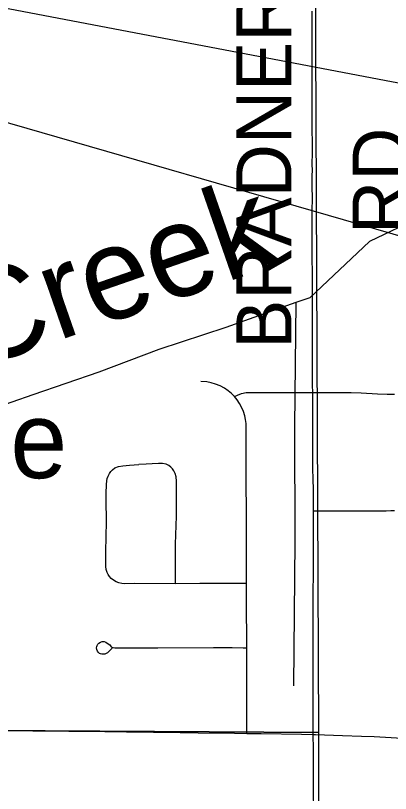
# Model space of a CAD drawing. Extents: x 0 to 34, y 0 to 22.
# Drawn here: x 3.392 to 3.778, y 19.337 to 20.14 of the extents above; entities that cross this region are included whole.
import ezdxf

# ---------------------------------------------------------------- set-up
doc = ezdxf.new("R2010")
doc.units = 0
for name, color, linetype in [('GM_X_Minor_River', 7, 'Continuous'), ('GM_X_Minor_River_Text', 7, 'Continuous'), ('GM_X_Section', 7, 'Continuous'), ('GM_X_Township_Road', 7, 'Continuous'), ('GM_X_Township_Road_Text', 7, 'Continuous'), ('GM_X_Unincorporated_Text', 7, 'Continuous'), ('SH_Text', 7, 'Continuous')]:
    doc.layers.add(name, color=color, linetype=linetype)

msp = doc.modelspace()

# ---------------------------------------------------------------- linework, layer by layer
at = {"layer": 'GM_X_Minor_River'}
for points in [[(3.80864, 19.93128), (3.7568, 19.9067), (3.69535, 19.8485), (3.6809, 19.8438), (3.609, 19.81802), (3.53978, 19.79523), (3.47813, 19.77194), (3.41004, 19.74837), (3.34499, 19.7259)], [(3.6809, 19.8438), (3.67964, 19.71596), (3.68002, 19.59719), (3.67843, 19.44848)]]:
    msp.add_lwpolyline(points, dxfattribs=at)
at = {"layer": 'GM_X_Section'}
for points in [[(3.7003, 20.3485), (3.70416, 19.40015), (2.69072, 19.40645), (2.6925, 20.35134)], [(2.69072, 19.40645), (3.70416, 19.40015), (3.70319, 18.38855), (2.69664, 18.40086)]]:
    msp.add_lwpolyline(points, close=True, dxfattribs=at)
at = {"layer": 'GM_X_Township_Road'}
for points in [[(3.69833, 19.75101), (3.69829, 19.75844), (3.69816, 19.78455), (3.69808, 19.80693), (3.69818, 19.83305), (3.69828, 19.85107), (3.69814, 19.87343), (3.69787, 19.89022), (3.69792, 19.9101), (3.69795, 19.93734), (3.69807, 19.95226), (3.69796, 19.96218), (3.69797, 19.97572), (3.69802, 19.97893), (3.69788, 19.98734), (3.69798, 19.99709), (3.69791, 20.03351), (3.69785, 20.04719), (3.69793, 20.06832), (3.69787, 20.08695), (3.69777, 20.11307), (3.69787, 20.14415)], [(3.6179, 19.74664), (3.61457, 19.74994), (3.61114, 19.75276), (3.60744, 19.75522), (3.60298, 19.75764), (3.5983, 19.75953), (3.59383, 19.76101), (3.58923, 19.7619), (3.58319, 19.76227)], [(3.6179, 19.74664), (3.62083, 19.74797), (3.6249, 19.74982), (3.62971, 19.75084), (3.63343, 19.75092), (3.69216, 19.751), (3.69833, 19.75101)], [(3.69915, 19.62888), (3.69906, 19.65152), (3.69867, 19.66084), (3.69856, 19.67328), (3.69852, 19.71742), (3.69833, 19.75101)], [(3.69833, 19.75101), (3.70884, 19.75086), (3.73784, 19.75078), (3.74841, 19.75043), (3.76517, 19.74934), (3.77513, 19.74908), (3.77575, 19.74908), (3.78254, 19.74909)], [(3.63022, 19.55405), (3.63028, 19.5601), (3.63031, 19.57181), (3.63012, 19.58309), (3.63018, 19.59681), (3.63005, 19.62229), (3.62984, 19.66398), (3.62968, 19.68386), (3.62991, 19.71184), (3.62973, 19.71875), (3.62926, 19.72316), (3.62848, 19.7269), (3.62712, 19.73114), (3.62514, 19.73579), (3.62306, 19.73971), (3.6206, 19.74342), (3.6179, 19.74664)], [(3.55709, 19.5536), (3.55707, 19.5633), (3.55703, 19.58068), (3.5571, 19.59434), (3.55793, 19.6235), (3.55817, 19.64895), (3.55821, 19.65952), (3.55778, 19.66384), (3.55676, 19.66741), (3.55537, 19.67018), (3.55391, 19.67217), (3.55219, 19.67397), (3.55025, 19.67552), (3.54757, 19.67709), (3.54377, 19.67765), (3.53958, 19.67765), (3.53292, 19.67727), (3.52687, 19.67703), (3.51934, 19.67665)], [(3.55709, 19.5536), (3.51481, 19.55381), (3.50486, 19.55366), (3.50175, 19.55393), (3.49872, 19.55459), (3.49582, 19.55571), (3.49313, 19.55726), (3.49073, 19.55923), (3.48907, 19.56109), (3.4877, 19.56317), (3.48666, 19.56542), (3.48577, 19.5684), (3.48534, 19.57148), (3.48527, 19.57832), (3.48536, 19.5889), (3.48575, 19.60009), (3.48579, 19.62), (3.48569, 19.63808), (3.48575, 19.63992), (3.48569, 19.64306), (3.48574, 19.64678), (3.48598, 19.6561), (3.48629, 19.65981), (3.48681, 19.66224), (3.48761, 19.66459), (3.489, 19.66737), (3.49042, 19.66941), (3.49211, 19.67123), (3.49455, 19.67316), (3.49824, 19.67455), (3.50269, 19.67517), (3.50972, 19.67591), (3.51934, 19.67665)], [(3.69899, 19.3982), (3.69897, 19.40258), (3.69895, 19.40776), (3.6988, 19.43061), (3.69878, 19.44553), (3.69889, 19.50238), (3.69894, 19.52724), (3.69888, 19.54776), (3.69903, 19.56081), (3.69917, 19.58567), (3.69918, 19.62297), (3.69915, 19.62888)], [(3.69915, 19.62888), (3.70271, 19.62888), (3.70851, 19.62887), (3.72308, 19.6288), (3.75158, 19.62894), (3.77403, 19.62902), (3.77885, 19.62904), (3.78264, 19.62906)], [(3.63022, 19.55405), (3.62422, 19.55404), (3.58195, 19.55397), (3.55709, 19.5536)], [(3.63045, 19.48764), (3.63035, 19.49419), (3.63035, 19.50973), (3.63027, 19.51534), (3.63015, 19.53087), (3.63016, 19.54705), (3.63022, 19.55405)], [(3.49183, 19.48716), (3.49059, 19.4858), (3.48874, 19.48407), (3.4869, 19.48234), (3.48414, 19.48122), (3.48232, 19.48088), (3.48108, 19.48096), (3.47989, 19.48131), (3.47879, 19.48188), (3.47783, 19.48267), (3.47669, 19.48416), (3.47597, 19.48588), (3.47572, 19.48772), (3.47586, 19.48896), (3.47626, 19.49013), (3.4769, 19.4912), (3.4782, 19.49253), (3.47981, 19.49349), (3.4816, 19.49399), (3.48346, 19.49396), (3.48521, 19.49338), (3.48677, 19.49235), (3.48923, 19.49061), (3.49084, 19.48876), (3.49232, 19.48777), (3.49455, 19.48764), (3.50264, 19.48759), (3.52069, 19.48743), (3.53878, 19.48771), (3.59634, 19.48794)], [(3.59634, 19.48794), (3.60531, 19.48804), (3.6153, 19.48791), (3.62682, 19.4877), (3.63045, 19.48764)], [(3.63035, 19.3993), (3.6304, 19.40648), (3.63055, 19.43136), (3.63048, 19.45438), (3.63055, 19.48111), (3.63045, 19.48764)], [(3.2409, 19.40431), (3.27083, 19.40369), (3.28452, 19.40365), (3.31063, 19.40331), (3.33674, 19.40316), (3.3815, 19.40259), (3.41008, 19.40206), (3.48428, 19.40124), (3.50666, 19.40086), (3.56188, 19.40019), (3.58052, 19.39999), (3.61783, 19.3995), (3.63035, 19.3993)], [(3.63035, 19.3993), (3.64513, 19.39908), (3.68677, 19.39839), (3.69899, 19.3982)], [(3.70013, 19.2969), (3.6996, 19.32332), (3.69931, 19.33638), (3.69934, 19.36001), (3.69911, 19.3832), (3.69899, 19.3982)], [(3.69899, 19.3982), (3.70108, 19.39817), (3.72901, 19.39721), (3.74871, 19.39645), (3.76175, 19.39599), (3.80213, 19.3939), (3.82759, 19.39258), (3.84496, 19.39156), (3.88782, 19.38965), (3.91763, 19.38806), (3.95107, 19.38591), (4.01674, 19.3821), (4.04094, 19.38059), (4.07385, 19.37898), (4.15204, 19.37428), (4.1862, 19.37261), (4.20284, 19.37198)]]:
    msp.add_lwpolyline(points, dxfattribs=at)
at = {"layer": 'SH_Text'}
msp.add_lwpolyline([(9.21814, 19.03459), (2.19045, 20.37443), (9.21814, 18.3428)], close=True, dxfattribs=at)

# ---------------------------------------------------------------- texts
at = {"layer": 'GM_X_Minor_River_Text'}
msp.add_text('Creek', height=0.09476, rotation=19.19546, dxfattribs=at).set_placement((3.34887, 19.77384))
at = {"layer": 'GM_X_Township_Road_Text'}
for s, p in [('BRADNER', (3.67649, 19.79595)), ('RD', (3.7963, 19.91428))]:
    msp.add_text(s, height=0.056818, rotation=90, dxfattribs=at).set_placement(p)
at = {"layer": 'GM_X_Unincorporated_Text'}
msp.add_text('Woodville', height=0.078977, rotation=0.00001, dxfattribs=at).set_placement((2.9878, 19.66258))

doc.saveas('drawing.dxf')
